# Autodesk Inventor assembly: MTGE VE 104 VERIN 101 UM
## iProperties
Shininess: 41.0
Angle Display Precision: 2
Document Length Units: 11269
Document Angle Units: 11279
Document Time Units: 11290
Document Mass Units: 11283
Document Length Units Precision: 3
Document Angle Units Precision: 2
Part Number: MTGE VE 104 VERIN 101 UM
Document SubType Name: Assembly
Density: 0.0
Volumn: 0.0
Area: 0.0
PropertySet Name: Model Information
Control State: 0
Master: False
Checked Out: False
